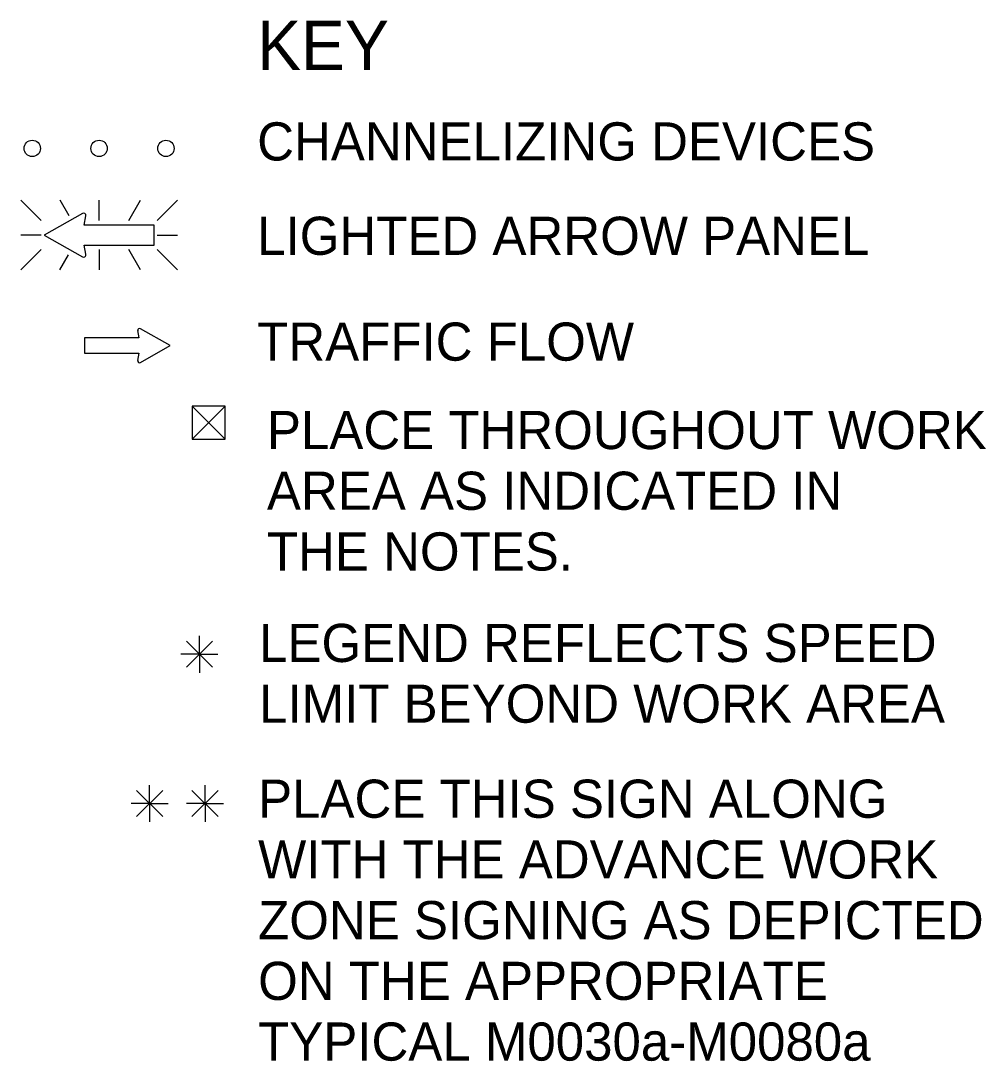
# Model space of a CAD drawing. Extents: x 16724 to 19508, y 5703 to 6974.
# Drawn here: x 18220.7 to 18456, y 6661.1 to 6914.7 of the extents above; entities that cross this region are included whole.
import ezdxf

# ---------------------------------------------------------------- set-up
doc = ezdxf.new("R2010")
doc.units = 0
for name, color, linetype in [('MT_SCRATCH_LEVEL_E', 7, 'Continuous'), ('TRAFFIC_SIGNS_PR', 7, 'Continuous'), ('TYPICAL_TEXT_DIMEN_EX', 7, 'Continuous'), ('TYPICAL_TEXT_DIMEN_PR', 7, 'Continuous')]:
    doc.layers.add(name, color=color, linetype=linetype)

msp = doc.modelspace()

# ---------------------------------------------------------------- linework, layer by layer
at = {"layer": 'MT_SCRATCH_LEVEL_E'}
for p, q in [((18257.07, 6835.54), (18249.83, 6839.65)), ((18249.46, 6837.39), (18236.2, 6837.39)), ((18236.2, 6837.39), (18236.2, 6833.65)), ((18249.14, 6839.17), (18249.46, 6837.39)), ((18249.83, 6831.39), (18257.07, 6835.54)), ((18236.2, 6833.65), (18249.46, 6833.65)), ((18249.46, 6833.65), (18249.14, 6831.87))]:
    msp.add_line(p, q, dxfattribs=at)
for centre, start, end in [((18249.6, 6839.24), 60.4248, 189.9638), ((18249.6, 6831.8), 170.0362, 299.7731)]:
    msp.add_arc(centre, 0.463, start, end, dxfattribs=at)
at = {"layer": 'TRAFFIC_SIGNS_PR'}
for p, q in [((18220.65, 6870.97), (18225.58, 6866.03)), ((18232.41, 6867.15), (18230.21, 6870.97)), ((18239.73, 6866.03), (18239.73, 6870.97)), ((18246.97, 6866.03), (18249.82, 6870.97)), ((18253.88, 6866.03), (18258.82, 6870.97)), ((18225.58, 6862.48), (18220.65, 6862.48)), ((18253.88, 6862.48), (18258.82, 6862.48)), ((18220.65, 6853.99), (18225.58, 6858.92)), ((18230.16, 6853.99), (18232.27, 6857.65)), ((18239.73, 6858.92), (18239.73, 6853.99)), ((18249.86, 6853.99), (18247.01, 6858.92)), ((18253.88, 6858.92), (18258.82, 6853.99))]:
    msp.add_line(p, q, dxfattribs=at)
for points in [[(18235.66, 6867.75), (18226.37, 6862.48), (18235.66, 6857.16)], [(18236.54, 6857.78), (18236.14, 6860.05), (18253.15, 6860.05), (18253.15, 6864.85), (18236.14, 6864.85), (18236.54, 6867.14)]]:
    msp.add_lwpolyline(points, dxfattribs=at)
for centre in [(18223.44, 6883.59), (18239.74, 6883.59), (18256.04, 6883.59)]:
    msp.add_circle(centre, 2, dxfattribs=at)
for centre, radius, start, end in [((18235.95, 6867.23), 0.598, 350.7308, 118.8916), ((18235.95, 6857.68), 0.597, 241.4833, 9.9593)]:
    msp.add_arc(centre, radius, start, end, dxfattribs=at)
at = {"layer": 'TYPICAL_TEXT_DIMEN_PR'}
for p, q in [((18262.44, 6812.74), (18270.44, 6820.74)), ((18262.45, 6820.74), (18270.44, 6812.74)), ((18264.2, 6760.3), (18264.2, 6764.76)), ((18261.01, 6763.49), (18267.39, 6757.11)), ((18267.39, 6763.49), (18261.01, 6757.11)), ((18264.2, 6760.3), (18259.67, 6760.3)), ((18264.2, 6760.3), (18267.39, 6760.3)), ((18264.2, 6760.3), (18268.68, 6760.3)), ((18264.2, 6760.3), (18264.2, 6755.8)), ((18252.06, 6723.93), (18252.06, 6728.38)), ((18265.57, 6723.93), (18265.57, 6728.38)), ((18255.25, 6727.12), (18248.87, 6720.74)), ((18248.88, 6727.12), (18255.25, 6720.74)), ((18262.38, 6727.12), (18268.76, 6720.74)), ((18268.76, 6727.12), (18262.38, 6720.74)), ((18252.06, 6723.93), (18247.53, 6723.93)), ((18252.06, 6723.93), (18255.25, 6723.93)), ((18252.06, 6723.93), (18256.54, 6723.93)), ((18252.06, 6723.93), (18252.06, 6719.43)), ((18265.57, 6723.93), (18261.03, 6723.93)), ((18265.57, 6723.93), (18268.76, 6723.93)), ((18265.57, 6723.93), (18270.05, 6723.93)), ((18265.57, 6723.93), (18265.57, 6719.43))]:
    msp.add_line(p, q, dxfattribs=at)
msp.add_lwpolyline([(18262.45, 6820.74), (18262.44, 6812.74), (18270.44, 6812.74), (18270.44, 6820.74)], close=True, dxfattribs=at)
msp.add_open_spline([(18357.15, 6760.89), (18357.17, 6760.89), (18357.18, 6760.89), (18357.18, 6760.89)], degree=2, dxfattribs=at)

# ---------------------------------------------------------------- texts
at = {"layer": 'TYPICAL_TEXT_DIMEN_EX'}
for s, height, p in [('KEY', 12, (18278.28, 6902.7)), ('CHANNELIZING DEVICES', 9.3, (18278.28, 6880.65)), ('LIGHTED ARROW PANEL', 9.3, (18278.28, 6857.65)), ('TRAFFIC FLOW', 9.3, (18278.28, 6831.85)), ('PLACE THROUGHOUT WORK', 9.3, (18280.66, 6810.3)), ('AREA AS INDICATED IN', 9.3, (18280.66, 6795.5)), ('THE NOTES.', 9.3, (18280.66, 6780.7)), ('LEGEND REFLECTS SPEED', 9.3, (18278.75, 6758.4)), ('LIMIT BEYOND WORK AREA', 9.3, (18278.75, 6743.6)), ('PLACE THIS SIGN ALONG', 9.3, (18278.51, 6720.43)), ('WITH THE ADVANCE WORK', 9.3, (18278.51, 6705.63)), ('ZONE SIGNING AS DEPICTED', 9.3, (18278.51, 6690.83)), ('ON THE APPROPRIATE', 9.3, (18278.51, 6676.03)), ('TYPICAL M0030a-M0080a', 9.3, (18278.51, 6661.23))]:
    msp.add_text(s, height=height, dxfattribs=at).set_placement(p)

doc.saveas('drawing.dxf')
